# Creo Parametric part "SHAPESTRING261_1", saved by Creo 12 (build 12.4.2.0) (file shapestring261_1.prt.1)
Units: Custom; MM, KILOGRAM, SECS

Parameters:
  PTC_WM_ITERATION = "0"
  PTC_WM_VERSION = "-.0"
  PTC_WM_LIFECYCLE_STATE = "In Work"
  PTC_WM_LIFECYCLE = "MO_CADDocument"
  PTC_WM_CREATED_BY = "Maximilian Roepper (Z0017RMS: MO)"
  PTC_WM_CREATED_ON = "18-Sep-26 11:36:42 AM"
  PTC_WM_MODIFIED_BY = "Maximilian Roepper (Z0017RMS: MO)"
  PTC_WM_MODIFIED_ON = "18-Sep-26 11:36:46 AM"
  PDMLINKNUMBER = "PDM000071455079"
  PTC_WM_NAME = "shapestring261_1.prt"
  PTC_WM_NUMBER = "PDM000071455079"

Other parameters: WEIGHT, WEIGHT_FACTOR, WEIGHT_ADD, _MASS_TEMP, _DIFF_TEMP, MC_ERRORS, SUPPLIER

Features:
  1. coordinate system
  2. datum plane "PRT_YZ"
  3. datum plane "PRT_XY"
  4. datum plane "PRT_XZ"
  5. coordinate system
  6. datum axis
  7. datum axis
  8. datum axis
  9. coordinate system
  10. imported feature
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
Other named items: PRT, SIEMENS_MO, DRW_VIEW_ORG, PRT_X, PRT_Y, PRT_Z, CS0, ROUGH_GROB

Layers: 00_STD_CSYS-KSYS, 01_STD_PLANES-EBENEN, 02_STD_AXES-ACHSEN, 03_STD_CSYS-KSYS, 24_IMPORT_FEAT-IMPORT_KE, WHITE

Surfaces: 1 plane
